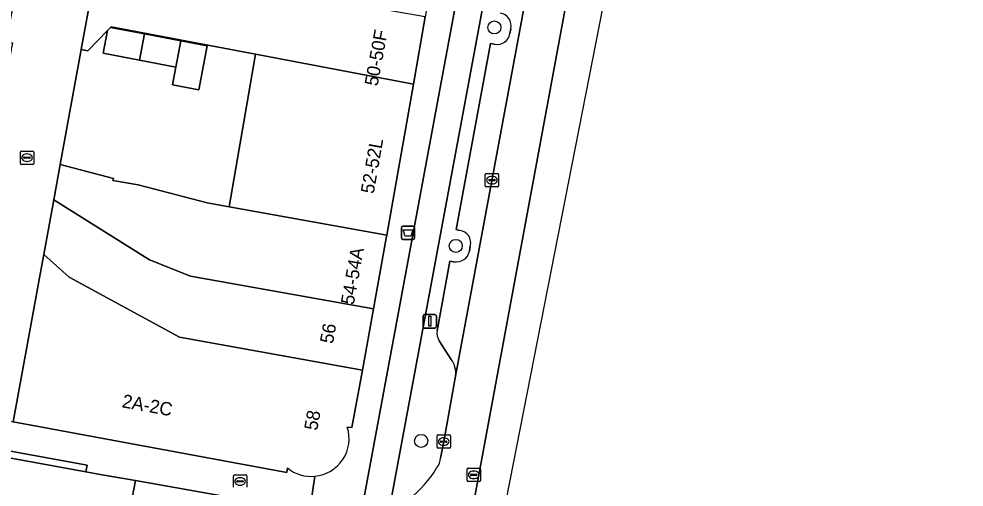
# Model space of a CAD drawing. Extents: x 161402 to 161933, y 381647 to 382315.
# Drawn here: x 161862.2 to 161933.1, y 381943.5 to 381978.6 of the extents above; entities that cross this region are included whole.
import ezdxf

# ---------------------------------------------------------------- set-up
doc = ezdxf.new("R2010")
doc.units = 0
for name, color, linetype in [('IMGEO_Afvalbak', 7, 'Continuous'), ('IMGEO_Boom', 7, 'Continuous'), ('IMGEO_Brandkraan', 7, 'Continuous'), ('IMGEO_Erf', 7, 'Continuous'), ('IMGEO_Fietspad_gesloten', 7, 'Continuous'), ('IMGEO_Kolk', 7, 'Continuous'), ('IMGEO_Lichtmast', 7, 'Continuous'), ('IMGEO_OVBaan_gesloten', 7, 'Continuous'), ('IMGEO_Pand', 7, 'Continuous'), ('IMGEO_Pand_nummerreeks', 7, 'Continuous'), ('IMGEO_Parkeervlak_open', 7, 'Continuous'), ('IMGEO_Rijbaan_lokaal_gesloten', 7, 'Continuous'), ('IMGEO_Rijbaan_lokaal_open', 7, 'Continuous'), ('IMGEO_Rioolput', 7, 'Continuous'), ('IMGEO_Verkeerseiland_open', 7, 'Continuous'), ('IMGEO_Voetpad_open', 7, 'Continuous')]:
    doc.layers.add(name, color=color, linetype=linetype)

msp = doc.modelspace()

# ---------------------------------------------------------------- linework, layer by layer
at = {"layer": 'IMGEO_Afvalbak'}
for p, q in [((161890.918, 381962.208), (161890.918, 381963.008)), ((161890.918, 381963.008), (161890.918, 381962.208)), ((161891.018, 381963.108), (161891.808, 381963.108)), ((161891.808, 381963.108), (161891.018, 381963.108)), ((161891.908, 381963.008), (161891.908, 381962.208)), ((161891.908, 381962.208), (161891.908, 381963.008)), ((161891.808, 381962.108), (161891.018, 381962.108)), ((161891.018, 381962.108), (161891.808, 381962.108))]:
    msp.add_line(p, q, dxfattribs=at)
msp.add_lwpolyline([(161891.061, 381962.822), (161891.765, 381962.822), (161891.616, 381962.352), (161891.21, 381962.352), (161891.061, 381962.822)], dxfattribs=at)
for centre, start, end in [((161891.018, 381963.008), 90, 180), ((161891.018, 381963.008), 90, 180), ((161891.808, 381963.008), 0, 90), ((161891.808, 381963.008), 360, 90), ((161891.018, 381962.208), 180, 270), ((161891.018, 381962.208), 180, 270), ((161891.808, 381962.208), 270, 0), ((161891.808, 381962.208), 270, 0)]:
    msp.add_arc(centre, 0.1, start, end, dxfattribs=at)
at = {"layer": 'IMGEO_Boom'}
for centre in [(161897.888, 381978.002), (161894.996, 381961.627), (161892.4, 381947.013)]:
    msp.add_circle(centre, 0.489, dxfattribs=at)
at = {"layer": 'IMGEO_Brandkraan'}
for p, q in [((161878.324, 381943.55), (161878.324, 381944.402)), ((161878.399, 381944.476), (161879.251, 381944.476)), ((161879.325, 381944.402), (161879.325, 381943.55)), ((161878.583, 381943.97), (161878.583, 381943.982)), ((161879.021, 381943.933), (161878.623, 381943.933)), ((161878.626, 381944.019), (161879.024, 381944.019)), ((161878.835, 381943.696), (161878.81, 381943.696)), ((161878.812, 381944.256), (161878.837, 381944.256)), ((161879.067, 381943.982), (161879.067, 381943.97))]:
    msp.add_line(p, q, dxfattribs=at)
for points in [[(161878.324, 381943.55), (161878.324, 381944.402)], [(161878.399, 381944.476), (161879.251, 381944.476)], [(161879.325, 381944.402), (161879.325, 381943.55)]]:
    msp.add_lwpolyline(points, dxfattribs=at)
for centre, radius, start, end in [((161878.401, 381944.4), 0.0765, 91.55205, 178.44795), ((161878.401, 381944.4), 0.0765, 91.55205, 178.44795), ((161879.249, 381944.4), 0.0765, 1.55205, 88.44795), ((161879.249, 381944.4), 0.0765, 1.55205, 88.44795), ((161878.623, 381943.979), 0.0403, 85.87752, 175.75265), ((161878.62, 381943.969), 0.0366, 178.93798, 274.71019), ((161879.024, 381943.976), 0.043, 264.86636, 352.45326), ((161879.028, 381943.981), 0.0386, 1.73085, 96.63898)]:
    msp.add_arc(centre, radius, start, end, dxfattribs=at)
for centre, major_axis, ratio, start_param, end_param in [((161878.811, 381943.976), (-0.387, 0.002), 0.722429, 4.712389, 7.853982), ((161878.836, 381943.976), (-0.39, 0.002), 0.717154, 1.570796, 4.712389)]:
    msp.add_ellipse(centre, major_axis=major_axis, ratio=ratio, start_param=start_param, end_param=end_param, dxfattribs=at)
at = {"layer": 'IMGEO_Erf'}
msp.add_lwpolyline([(161879.974, 381976.006), (161869.163, 381978.052), (161869.113, 381978.001), (161871.661, 381977.517), (161874.391, 381976.998), (161876.362, 381976.624), (161875.737, 381973.333), (161873.767, 381973.707), (161874.02, 381975.038), (161871.29, 381975.554), (161868.56, 381976.07), (161868.882, 381977.766), (161867.399, 381976.257), (161866.912, 381976.352), (161865.345, 381967.728), (161869.324, 381966.69), (161869.297, 381966.539), (161871.19, 381966.203), (161876.349, 381964.857), (161878.016, 381964.558)], close=True, dxfattribs=at)
at = {"layer": 'IMGEO_Fietspad_gesloten'}
for points in [[(161910.061, 382061.001), (161905.702, 382037.375), (161898.752, 382000), (161887.89, 381941.593), (161886.669, 381935.154), (161880.56, 381902.497), (161879.486, 381896.758), (161857.65, 381780.798), (161851.928, 381750), (161842.232, 381697.819)], [(161881.54, 381896.271), (161882.623, 381902.093), (161888.398, 381933.147), (161890.059, 381942.083), (161900.83, 382000), (161908.061, 382038.88), (161912.039, 382060.567)]]:
    msp.add_lwpolyline(points, dxfattribs=at)
at = {"layer": 'IMGEO_Kolk'}
for p, q in [((161862.352, 381967.813), (161862.352, 381968.665)), ((161862.427, 381968.739), (161863.279, 381968.739)), ((161862.84, 381968.519), (161862.865, 381968.519)), ((161863.353, 381968.665), (161863.353, 381967.813)), ((161862.611, 381968.233), (161862.611, 381968.245)), ((161863.049, 381968.196), (161862.651, 381968.196)), ((161862.654, 381968.282), (161863.052, 381968.282)), ((161862.863, 381967.959), (161862.838, 381967.959)), ((161863.095, 381968.245), (161863.095, 381968.233)), ((161863.279, 381967.739), (161862.427, 381967.739)), ((161897.207, 381966.131), (161897.207, 381966.983)), ((161897.282, 381967.057), (161898.134, 381967.057)), ((161897.466, 381966.551), (161897.466, 381966.563)), ((161897.904, 381966.514), (161897.506, 381966.514)), ((161897.509, 381966.6), (161897.907, 381966.6)), ((161897.695, 381966.837), (161897.72, 381966.837)), ((161897.95, 381966.563), (161897.95, 381966.551)), ((161898.208, 381966.983), (161898.208, 381966.131)), ((161898.134, 381966.057), (161897.282, 381966.057)), ((161897.718, 381966.277), (161897.693, 381966.277)), ((161893.587, 381946.535), (161893.587, 381947.387)), ((161893.662, 381947.461), (161894.514, 381947.461)), ((161894.075, 381947.241), (161894.1, 381947.241)), ((161894.588, 381947.387), (161894.588, 381946.535)), ((161893.846, 381946.955), (161893.846, 381946.967)), ((161894.284, 381946.918), (161893.886, 381946.918)), ((161893.889, 381947.004), (161894.287, 381947.004)), ((161894.098, 381946.681), (161894.073, 381946.681)), ((161894.33, 381946.967), (161894.33, 381946.955)), ((161894.514, 381946.461), (161893.662, 381946.461))]:
    msp.add_line(p, q, dxfattribs=at)
for points in [[(161862.352, 381967.813), (161862.352, 381968.665)], [(161862.427, 381968.739), (161863.279, 381968.739)], [(161863.353, 381968.665), (161863.353, 381967.813)], [(161863.279, 381967.739), (161862.427, 381967.739)], [(161897.207, 381966.131), (161897.207, 381966.983)], [(161897.282, 381967.057), (161898.134, 381967.057)], [(161898.208, 381966.983), (161898.208, 381966.131)], [(161898.134, 381966.057), (161897.282, 381966.057)], [(161893.587, 381946.535), (161893.587, 381947.387)], [(161893.662, 381947.461), (161894.514, 381947.461)], [(161894.588, 381947.387), (161894.588, 381946.535)], [(161894.514, 381946.461), (161893.662, 381946.461)]]:
    msp.add_lwpolyline(points, dxfattribs=at)
for centre, radius, start, end in [((161862.429, 381968.663), 0.0765, 91.55205, 178.44795), ((161862.429, 381968.663), 0.0765, 91.55205, 178.44795), ((161863.277, 381968.663), 0.0765, 1.55205, 88.44795), ((161863.277, 381968.663), 0.0765, 1.55205, 88.44795), ((161862.429, 381967.815), 0.0765, 181.55205, 268.44795), ((161862.429, 381967.815), 0.0765, 181.55205, 268.44795), ((161862.651, 381968.242), 0.0403, 85.87752, 175.75265), ((161862.648, 381968.232), 0.0366, 178.93798, 274.71019), ((161863.052, 381968.239), 0.043, 264.86636, 352.45326), ((161863.056, 381968.244), 0.0386, 1.73085, 96.63898), ((161863.277, 381967.815), 0.0765, 271.55205, 358.44795), ((161863.277, 381967.815), 0.0765, 271.55205, 358.44795), ((161897.284, 381966.981), 0.0765, 91.55205, 178.44795), ((161897.284, 381966.981), 0.0765, 91.55205, 178.44795), ((161897.506, 381966.56), 0.0403, 85.87752, 175.75265), ((161897.503, 381966.55), 0.0366, 178.93798, 274.71019), ((161897.907, 381966.557), 0.043, 264.86636, 352.45326), ((161897.911, 381966.562), 0.0386, 1.73085, 96.63898), ((161898.132, 381966.981), 0.0765, 1.55205, 88.44795), ((161898.132, 381966.981), 0.0765, 1.55205, 88.44795), ((161897.284, 381966.133), 0.0765, 181.55205, 268.44795), ((161897.284, 381966.133), 0.0765, 181.55205, 268.44795), ((161898.132, 381966.133), 0.0765, 271.55205, 358.44795), ((161898.132, 381966.133), 0.0765, 271.55205, 358.44795), ((161893.664, 381947.385), 0.0765, 91.55205, 178.44795), ((161893.664, 381947.385), 0.0765, 91.55205, 178.44795), ((161894.512, 381947.385), 0.0765, 1.55205, 88.44795), ((161894.512, 381947.385), 0.0765, 1.55205, 88.44795), ((161893.664, 381946.537), 0.0765, 181.55205, 268.44795), ((161893.664, 381946.537), 0.0765, 181.55205, 268.44795), ((161893.886, 381946.964), 0.0403, 85.87752, 175.75265), ((161893.883, 381946.954), 0.0366, 178.93798, 274.71019), ((161894.287, 381946.961), 0.043, 264.86636, 352.45326), ((161894.291, 381946.966), 0.0386, 1.73085, 96.63898), ((161894.512, 381946.537), 0.0765, 271.55205, 358.44795), ((161894.512, 381946.537), 0.0765, 271.55205, 358.44795)]:
    msp.add_arc(centre, radius, start, end, dxfattribs=at)
for centre, major_axis, ratio, start_param, end_param in [((161862.839, 381968.239), (-0.387, 0.002), 0.722429, 4.712389, 7.853982), ((161862.864, 381968.239), (-0.39, 0.002), 0.717154, 1.570796, 4.712389), ((161897.694, 381966.557), (-0.387, 0.002), 0.722429, 4.712389, 7.853982), ((161897.719, 381966.557), (-0.39, 0.002), 0.717154, 1.570796, 4.712389), ((161894.074, 381946.961), (-0.387, 0.002), 0.722429, 4.712389, 7.853982), ((161894.099, 381946.961), (-0.39, 0.002), 0.717154, 1.570796, 4.712389)]:
    msp.add_ellipse(centre, major_axis=major_axis, ratio=ratio, start_param=start_param, end_param=end_param, dxfattribs=at)
at = {"layer": 'IMGEO_Lichtmast'}
for p, q in [((161892.648, 381956.475), (161893.438, 381956.475)), ((161893.438, 381956.475), (161892.648, 381956.475)), ((161892.548, 381955.575), (161892.548, 381956.375)), ((161892.548, 381956.375), (161892.548, 381955.575)), ((161893.538, 381956.375), (161893.538, 381955.575)), ((161893.538, 381955.575), (161893.538, 381956.375)), ((161893.438, 381955.475), (161892.648, 381955.475)), ((161892.648, 381955.475), (161893.438, 381955.475))]:
    msp.add_line(p, q, dxfattribs=at)
msp.add_lwpolyline([(161892.968, 381956.35), (161893.118, 381956.35), (161893.118, 381955.6), (161892.968, 381955.6), (161892.968, 381956.35)], dxfattribs=at)
for centre, start, end in [((161892.648, 381956.375), 90, 180), ((161892.648, 381956.375), 90, 180), ((161893.438, 381956.375), 0, 90), ((161893.438, 381956.375), 360, 90), ((161892.648, 381955.575), 180, 270), ((161892.648, 381955.575), 180, 270), ((161893.438, 381955.575), 270, 0), ((161893.438, 381955.575), 270, 0)]:
    msp.add_arc(centre, 0.1, start, end, dxfattribs=at)
at = {"layer": 'IMGEO_OVBaan_gesloten'}
for points in [[(161847.327, 381677.629), (161847.814, 381679.325), (161869.795, 381786.79), (161883.773, 381866.122), (161911.481, 382007.357), (161916.93, 382035.129), (161933.101, 382124.399), (161931.462, 382125.963), (161930.949, 382121.39)], [(161929.574, 382113.249), (161927.659, 382104.365), (161926.989, 382101.276), (161926.695, 382099.95), (161920.797, 382074.121), (161920.568, 382072.989), (161920.066, 382070.485), (161894.174, 381930.698), (161894.155, 381930.593), (161893.956, 381929.536), (161893.492, 381927.072), (161889.963, 381908.334), (161866.208, 381782.197), (161866.199, 381782.149), (161865.069, 381776.053), (161864.537, 381773.18), (161864.311, 381771.961), (161856.328, 381728.885)]]:
    msp.add_lwpolyline(points, dxfattribs=at)
at = {"layer": 'IMGEO_Pand'}
for points in [[(161880.283, 381980.984), (161874.288, 381986.095), (161874.432, 381986.902), (161869.626, 381991.167), (161866.912, 381976.352), (161867.399, 381976.257), (161868.882, 381977.766), (161869.113, 381978.001), (161869.163, 381978.052), (161879.974, 381976.006), (161891.821, 381973.764), (161892.707, 381978.796)], [(161871.661, 381977.517), (161869.113, 381978.001), (161868.882, 381977.766), (161868.56, 381976.07), (161871.29, 381975.554)], [(161874.391, 381976.998), (161871.661, 381977.517), (161871.29, 381975.554), (161874.02, 381975.038)], [(161876.362, 381976.624), (161874.391, 381976.998), (161874.02, 381975.038), (161873.767, 381973.707), (161875.737, 381973.333)], [(161891.821, 381973.764), (161879.974, 381976.006), (161878.016, 381964.558), (161889.826, 381962.441)], [(161878.016, 381964.558), (161876.349, 381964.857), (161871.19, 381966.203), (161869.297, 381966.539), (161869.324, 381966.69), (161865.345, 381967.728), (161864.865, 381965.088), (161872.033, 381960.597), (161875.112, 381959.372), (161888.825, 381956.914), (161889.787, 381962.219), (161889.826, 381962.441)], [(161888.825, 381956.914), (161875.112, 381959.372), (161872.033, 381960.597), (161864.865, 381965.088), (161864.117, 381960.973), (161866.008, 381959.287), (161874.288, 381954.778), (161887.991, 381952.322)]]:
    msp.add_lwpolyline(points, close=True, dxfattribs=at)
for points in [[(161874.288, 381954.778), (161866.008, 381959.287), (161864.117, 381960.973), (161864.023, 381960.454), (161861.825, 381948.441), (161882.328, 381944.651), (161882.378, 381944.986)], [(161886.859, 381948.049), (161887.211, 381948.02), (161887.991, 381952.322), (161874.288, 381954.778)]]:
    msp.add_lwpolyline(points, dxfattribs=at)
for centre, start, end in [((161884.166, 381947.18), 275.43474, 17.88384), ((161884.165, 381947.18), 230.83592, 275.44883)]:
    msp.add_arc(centre, 2.83, start, end, dxfattribs=at)
at = {"layer": 'IMGEO_Parkeervlak_open'}
for points in [[(161894.985, 381951.871), (161903.912, 382000), (161910.924, 382037.806), (161917.217, 382071.563)], [(161899.116, 381977.908), (161899.053, 381977.553)], [(161897.892, 381976.746), (161897.605, 381976.788), (161895.024, 381962.853), (161895.3, 381962.787)], [(161896.083, 381961.611), (161896.015, 381961.233)], [(161894.847, 381960.44), (161894.542, 381960.484), (161893.594, 381955.273)], [(161893.761, 381954.508), (161894.652, 381953.123)]]:
    msp.add_lwpolyline(points, dxfattribs=at)
msp.add_lwpolyline([(161878.707, 381942.675), (161870.982, 381944.038), (161870.647, 381942.219), (161882.653, 381940.012), (161882.997, 381941.882), (161882.65, 381941.962)], close=True, dxfattribs=at)
for centre, radius, start, end in [((161898.185, 381978.134), 0.958, 346.34412, 81.88699), ((161898.094, 381977.694), 0.969, 257.97827, 351.62732), ((161895.194, 381961.868), 0.925, 343.88515, 83.4275), ((161895.022, 381961.439), 1.014, 260.04779, 348.30039), ((161894.744, 381955.123), 1.16, 172.59025, 212.03878), ((161893.209, 381952.069), 1.787, 353.64403, 36.14473)]:
    msp.add_arc(centre, radius, start, end, dxfattribs=at)
at = {"layer": 'IMGEO_Rijbaan_lokaal_gesloten'}
for points in [[(161894.174, 381930.698), (161920.066, 382070.485), (161920.568, 382072.989), (161920.797, 382074.121), (161926.695, 382099.95)], [(161917.217, 382071.563), (161910.924, 382037.806), (161903.912, 382000), (161894.985, 381951.871), (161894.088, 381946.96), (161893.853, 381945.73)]]:
    msp.add_lwpolyline(points, dxfattribs=at)
for centre, radius, start, end in [((161892.563, 381945.8), 1.292, 322.36023, 356.8949), ((161886.286, 381949.364), 8.499, 307.87338, 329.19248)]:
    msp.add_arc(centre, radius, start, end, dxfattribs=at)
at = {"layer": 'IMGEO_Rijbaan_lokaal_open'}
for points in [[(161866.912, 381976.352), (161869.626, 381991.167), (161871.026, 381998.811), (161866.018, 381999.693), (161865.428, 381999.797), (161863.999, 381991.661), (161862.491, 381983.458), (161861.636, 381978.805), (161861.321, 381976.94), (161861.755, 381976.855), (161861.686, 381976.481), (161861.08, 381973.179), (161858.562, 381958.352), (161857.033, 381949.323), (161861.825, 381948.441), (161864.023, 381960.454), (161864.117, 381960.973), (161864.865, 381965.088), (161865.345, 381967.728)], [(161870.982, 381944.038), (161868.335, 381944.505), (161867.265, 381944.7), (161856.849, 381946.602), (161850.705, 381947.765), (161850.381, 381946.002), (161843.908, 381947.189), (161843.358, 381944.434), (161851.839, 381942.835), (161855.435, 381942.157), (161856.984, 381941.865), (161861.026, 381941.093), (161870.929, 381939.2), (161877.762, 381937.889), (161882.94, 381936.934), (161883.165, 381936.881), (161884.023, 381941.644), (161882.997, 381941.882), (161882.653, 381940.012), (161870.647, 381942.219)]]:
    msp.add_lwpolyline(points, close=True, dxfattribs=at)
at = {"layer": 'IMGEO_Rioolput'}
for p, q in [((161895.837, 381944.046), (161895.837, 381944.898)), ((161895.912, 381944.972), (161896.764, 381944.972)), ((161896.096, 381944.466), (161896.096, 381944.478)), ((161896.534, 381944.429), (161896.136, 381944.429)), ((161896.139, 381944.515), (161896.537, 381944.515)), ((161896.325, 381944.752), (161896.35, 381944.752)), ((161896.58, 381944.478), (161896.58, 381944.466)), ((161896.838, 381944.898), (161896.838, 381944.046)), ((161896.764, 381943.972), (161895.912, 381943.972)), ((161896.348, 381944.192), (161896.323, 381944.192))]:
    msp.add_line(p, q, dxfattribs=at)
for points in [[(161895.837, 381944.046), (161895.837, 381944.898)], [(161895.912, 381944.972), (161896.764, 381944.972)], [(161896.838, 381944.898), (161896.838, 381944.046)], [(161896.764, 381943.972), (161895.912, 381943.972)]]:
    msp.add_lwpolyline(points, dxfattribs=at)
for centre, radius, start, end in [((161895.914, 381944.896), 0.0765, 91.55205, 178.44795), ((161895.914, 381944.896), 0.0765, 91.55205, 178.44795), ((161896.136, 381944.475), 0.0403, 85.87752, 175.75265), ((161896.133, 381944.465), 0.0366, 178.93798, 274.71019), ((161896.537, 381944.472), 0.043, 264.86636, 352.45326), ((161896.541, 381944.477), 0.0386, 1.73085, 96.63898), ((161896.762, 381944.896), 0.0765, 1.55205, 88.44795), ((161896.762, 381944.896), 0.0765, 1.55205, 88.44795), ((161895.914, 381944.048), 0.0765, 181.55205, 268.44795), ((161895.914, 381944.048), 0.0765, 181.55205, 268.44795), ((161896.762, 381944.048), 0.0765, 271.55205, 358.44795), ((161896.762, 381944.048), 0.0765, 271.55205, 358.44795)]:
    msp.add_arc(centre, radius, start, end, dxfattribs=at)
for centre, major_axis, ratio, start_param, end_param in [((161896.324, 381944.472), (-0.387, 0.002), 0.722429, 4.712389, 7.853982), ((161896.349, 381944.472), (-0.39, 0.002), 0.717154, 1.570796, 4.712389)]:
    msp.add_ellipse(centre, major_axis=major_axis, ratio=ratio, start_param=start_param, end_param=end_param, dxfattribs=at)
at = {"layer": 'IMGEO_Verkeerseiland_open'}
for points in [[(161912.039, 382060.567), (161908.061, 382038.88), (161900.83, 382000), (161890.059, 381942.083), (161888.398, 381933.147), (161882.623, 381902.093), (161881.54, 381896.271), (161869.899, 381834.602), (161872.587, 381834.08), (161872.769, 381835.211)], [(161899.053, 381977.553), (161899.116, 381977.908)], [(161895.3, 381962.787), (161895.024, 381962.853), (161897.605, 381976.788), (161897.892, 381976.746)], [(161896.015, 381961.233), (161896.083, 381961.611)], [(161893.594, 381955.273), (161894.542, 381960.484), (161894.847, 381960.44)], [(161894.652, 381953.123), (161893.761, 381954.508)], [(161893.853, 381945.73), (161894.088, 381946.96), (161894.985, 381951.871)]]:
    msp.add_lwpolyline(points, dxfattribs=at)
for centre, radius, start, end in [((161898.185, 381978.134), 0.958, 346.34412, 81.88699), ((161898.094, 381977.694), 0.969, 257.97827, 351.62732), ((161895.194, 381961.868), 0.925, 343.88515, 83.4275), ((161895.022, 381961.439), 1.014, 260.04779, 348.30039), ((161894.744, 381955.123), 1.16, 172.59025, 212.03878), ((161893.209, 381952.069), 1.787, 353.64403, 36.14473), ((161892.563, 381945.8), 1.292, 322.36023, 356.8949), ((161886.286, 381949.364), 8.499, 307.87338, 329.19248)]:
    msp.add_arc(centre, radius, start, end, dxfattribs=at)
at = {"layer": 'IMGEO_Voetpad_open'}
for points in [[(161907.56, 382076.762), (161907.356, 382074.185), (161905.504, 382047.572), (161905.48, 382047.22), (161903.899, 382038.59), (161902.704, 382032.073), (161900.585, 382020.509), (161898.721, 382010.338), (161897.556, 382003.977), (161896.827, 382000), (161896.379, 381997.555), (161895.455, 381992.511), (161894.351, 381986.526), (161893.665, 381984.233), (161892.707, 381978.796), (161891.821, 381973.764), (161889.826, 381962.441), (161889.787, 381962.219), (161888.825, 381956.914), (161887.991, 381952.322), (161887.211, 381948.02), (161886.859, 381948.049)], [(161887.89, 381941.593), (161898.752, 382000), (161905.702, 382037.375), (161910.061, 382061.001)], [(161825.144, 381952.573), (161826.853, 381952.245), (161835.816, 381950.524), (161841.561, 381949.474), (161844.266, 381948.98), (161844.817, 381948.879), (161850.705, 381947.765), (161856.849, 381946.602), (161856.934, 381947.094), (161867.35, 381945.192), (161867.265, 381944.7), (161868.335, 381944.505), (161870.982, 381944.038), (161878.707, 381942.675), (161882.65, 381941.962), (161882.997, 381941.882), (161884.023, 381941.644), (161884.434, 381944.363)], [(161882.378, 381944.986), (161882.328, 381944.651), (161861.825, 381948.441)], [(161884.434, 381944.363), (161884.023, 381941.644), (161884.837, 381941.542)]]:
    msp.add_lwpolyline(points, dxfattribs=at)
msp.add_lwpolyline([(161856.934, 381947.094), (161856.849, 381946.602), (161867.265, 381944.7), (161867.35, 381945.192)], close=True, dxfattribs=at)
for centre, start, end in [((161884.166, 381947.18), 275.43474, 17.88384), ((161884.165, 381947.18), 230.83592, 275.44883)]:
    msp.add_arc(centre, 2.83, start, end, dxfattribs=at)

# ---------------------------------------------------------------- texts
at = {"layer": 'IMGEO_Pand_nummerreeks'}
for s, rotation, p in [('50-50F', 79.48643, (161889.128, 381973.559)), ('52-52L', 80.00783, (161888.84, 381965.49)), ('54-54A', 79.72135, (161887.346, 381957.168)), ('56', 79.70613, (161885.781, 381954.255)), ('2A-2C', 349.57217, (161869.923, 381949.539)), ('58', 79.72135, (161884.6, 381947.744))]:
    msp.add_text(s, height=1, rotation=rotation, dxfattribs=at).set_placement(p)

doc.saveas('drawing.dxf')
